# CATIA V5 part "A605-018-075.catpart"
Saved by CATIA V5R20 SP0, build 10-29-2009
Part number: A605-018-075
Source: Unknown
Property "A": "0.000"
Property "ARTICLENO": "A605-018-075"
Property "BOMINFO": "A605-018-075"
Property "CODE": "A605-018-075"
Property "D": "6.500"
Property "FORM": "A"
Property "L": "75.000"
Property "L1": "45.000"
Property "LINA": "A605-018-075"
Property "NB": "A605-018-075"
Property "NBSYN": "$CODE."
Property "NN": "A605"
Property "NT": "Wear Plates, self-lubricating"
Property "SCREW": "2*M6X10"
Property "SUPPLIER": "CF"
Property "W": "18.000"
Bounding box of the stored display mesh (mm): x -18 to 0, y 0 to 5, z -75 to 0
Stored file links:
  C:\Users\Utente\Desktop\3D files A605\A605-018-075.catpart
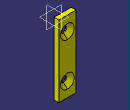
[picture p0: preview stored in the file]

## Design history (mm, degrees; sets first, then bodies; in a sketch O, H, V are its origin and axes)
Body1 "Geometry.1" (main body)
  Solid1 "A605-018-075.catpart": solid without history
